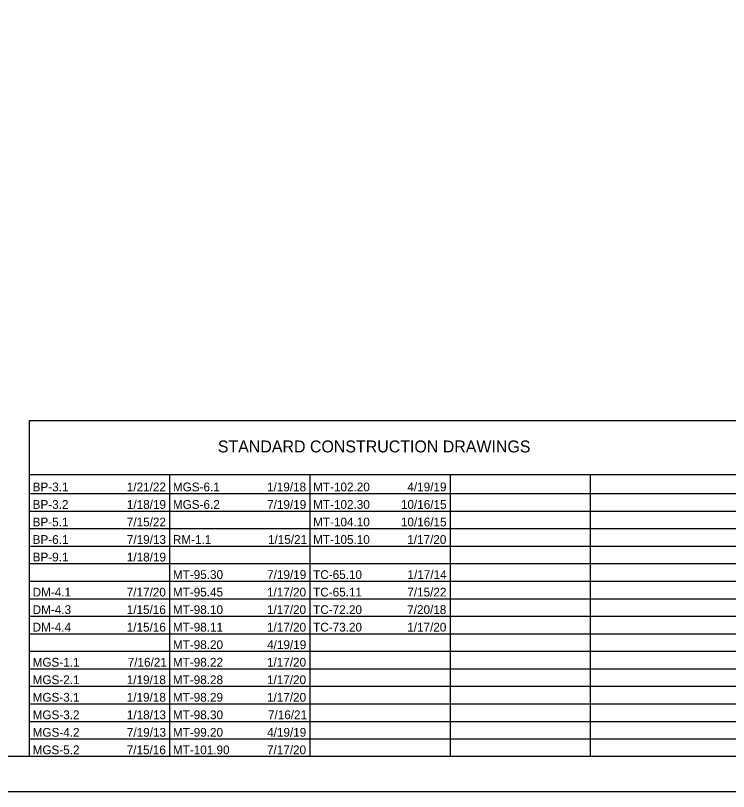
# Model space of a CAD drawing. Extents: x 0 to 34, y 0 to 22.
# Drawn here: x 9.95 to 20.12, y 0 to 11.07 of the extents above; entities that cross this region are included whole.
import ezdxf

# ---------------------------------------------------------------- set-up
doc = ezdxf.new("R2010")
doc.units = 0
for name, color, linetype in [('SH_Border', 7, 'Continuous'), ('SH_Cut_Line', 7, 'Continuous'), ('SH_Data', 7, 'Continuous'), ('SH_Text', 7, 'Continuous')]:
    doc.layers.add(name, color=color, linetype=linetype)

msp = doc.modelspace()

# ---------------------------------------------------------------- linework, layer by layer
at = {"layer": 'SH_Border'}
msp.add_lwpolyline([(1.5, 21.5), (33.5, 21.5), (33.5, 0.5), (1.5, 0.5)], close=True, dxfattribs=at)
at = {"layer": 'SH_Cut_Line'}
msp.add_lwpolyline([(0, 0), (34, 0), (34, 22), (0, 22)], close=True, dxfattribs=at)
at = {"layer": 'SH_Data'}
for p, q in [((10.15, 5.292), (23.6, 5.292)), ((10.15, 0.5), (10.15, 5.292)), ((10.15, 4.521), (23.6, 4.521)), ((12.15, 0.5), (12.15, 4.521)), ((14.15, 0.5), (14.15, 4.521)), ((16.15, 0.5), (16.15, 4.521)), ((18.15, 0.5), (18.15, 4.521)), ((10.15, 4.25), (23.6, 4.25)), ((10.15, 4), (23.6, 4)), ((10.15, 3.75), (23.6, 3.75)), ((10.15, 3.5), (23.6, 3.5)), ((10.15, 3.25), (23.6, 3.25)), ((10.15, 3), (23.6, 3)), ((10.15, 2.75), (23.6, 2.75)), ((10.15, 2.5), (23.6, 2.5)), ((10.15, 2.25), (23.6, 2.25)), ((10.15, 2), (23.6, 2)), ((10.15, 1.75), (23.6, 1.75)), ((10.15, 1.5), (23.6, 1.5)), ((10.15, 1.25), (23.6, 1.25)), ((10.15, 1), (23.6, 1)), ((10.15, 0.75), (23.6, 0.75))]:
    msp.add_line(p, q, dxfattribs=at)

# ---------------------------------------------------------------- texts
at = {"layer": 'SH_Text'}
for s, height, p in [('STANDARD CONSTRUCTION DRAWINGS', 0.17, (12.834, 4.836)), ('BP-3.1', 0.125, (10.193, 4.281)), ('1/21/22', 0.125, (11.536, 4.281)), ('MGS-6.1', 0.125, (12.193, 4.281)), ('1/19/18', 0.125, (13.535, 4.281)), ('MT-102.20', 0.125, (14.193, 4.281)), ('4/19/19', 0.125, (15.537, 4.281)), ('BP-3.2', 0.125, (10.193, 4.031)), ('1/18/19', 0.125, (11.537, 4.031)), ('MGS-6.2', 0.125, (12.193, 4.031)), ('7/19/19', 0.125, (13.537, 4.031)), ('MT-102.30', 0.125, (14.193, 4.031)), ('10/16/15', 0.125, (15.445, 4.031)), ('BP-5.1', 0.125, (10.193, 3.781)), ('7/15/22', 0.125, (11.536, 3.781)), ('MT-104.10', 0.125, (14.193, 3.781)), ('10/16/15', 0.125, (15.445, 3.781)), ('BP-6.1', 0.125, (10.193, 3.531)), ('7/19/13', 0.125, (11.537, 3.531)), ('RM-1.1', 0.125, (12.193, 3.531)), ('1/15/21', 0.125, (13.549, 3.531)), ('MT-105.10', 0.125, (14.193, 3.531)), ('1/17/20', 0.125, (15.535, 3.531)), ('BP-9.1', 0.125, (10.193, 3.281)), ('1/18/19', 0.125, (11.537, 3.281)), ('MT-95.30', 0.125, (12.193, 3.031)), ('7/19/19', 0.125, (13.537, 3.031)), ('TC-65.10', 0.125, (14.193, 3.031)), ('1/17/14', 0.125, (15.539, 3.031)), ('DM-4.1', 0.125, (10.193, 2.781)), ('7/17/20', 0.125, (11.535, 2.781)), ('MT-95.45', 0.125, (12.193, 2.781)), ('1/17/20', 0.125, (13.535, 2.781)), ('TC-65.11', 0.125, (14.193, 2.781)), ('7/15/22', 0.125, (15.536, 2.781)), ('DM-4.3', 0.125, (10.193, 2.531)), ('1/15/16', 0.125, (11.535, 2.531)), ('MT-98.10', 0.125, (12.193, 2.531)), ('1/17/20', 0.125, (13.535, 2.531)), ('TC-72.20', 0.125, (14.193, 2.531)), ('7/20/18', 0.125, (15.535, 2.531)), ('DM-4.4', 0.125, (10.193, 2.281)), ('1/15/16', 0.125, (11.535, 2.281)), ('MT-98.11', 0.125, (12.193, 2.281)), ('1/17/20', 0.125, (13.535, 2.281)), ('TC-73.20', 0.125, (14.193, 2.281)), ('1/17/20', 0.125, (15.535, 2.281)), ('MT-98.20', 0.125, (12.193, 2.031)), ('4/19/19', 0.125, (13.537, 2.031)), ('MGS-1.1', 0.125, (10.193, 1.781)), ('7/16/21', 0.125, (11.549, 1.781)), ('MT-98.22', 0.125, (12.193, 1.781)), ('1/17/20', 0.125, (13.535, 1.781)), ('1/19/18', 0.125, (11.535, 1.531)), ('1/17/20', 0.125, (13.535, 1.531)), ('MGS-2.1', 0.125, (10.193, 1.531)), ('MT-98.28', 0.125, (12.193, 1.531)), ('MGS-3.1', 0.125, (10.193, 1.281)), ('1/19/18', 0.125, (11.535, 1.281)), ('MT-98.29', 0.125, (12.193, 1.281)), ('1/17/20', 0.125, (13.535, 1.281)), ('MGS-3.2', 0.125, (10.193, 1.031)), ('1/18/13', 0.125, (11.537, 1.031)), ('MT-98.30', 0.125, (12.193, 1.031)), ('7/16/21', 0.125, (13.549, 1.031)), ('MGS-4.2', 0.125, (10.193, 0.781)), ('7/19/13', 0.125, (11.537, 0.781)), ('MT-99.20', 0.125, (12.193, 0.781)), ('4/19/19', 0.125, (13.537, 0.781)), ('MGS-5.2', 0.125, (10.193, 0.531)), ('7/15/16', 0.125, (11.535, 0.531)), ('MT-101.90', 0.125, (12.193, 0.531)), ('7/17/20', 0.125, (13.535, 0.531))]:
    msp.add_text(s, height=height, dxfattribs=at).set_placement(p)

doc.saveas('drawing.dxf')
